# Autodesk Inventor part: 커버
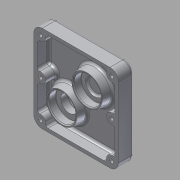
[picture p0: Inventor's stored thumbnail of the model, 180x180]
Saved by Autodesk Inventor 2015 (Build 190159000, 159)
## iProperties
Created: 2015-10
Part Number: 커버
Material: 알루미늄 6061
Document SubType Name: Modeling
Designer: mduedu
Density: 2.71 g/cm^3
Mass: 254.006 g
Surface Area: 401.286 cm^2
Volume: 93.729 cm^3
Appearance: 알루미늄 - 평지
Author: mduedu
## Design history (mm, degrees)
sketch "스케치1"
  geometry: L1 (-50, -51.5)-(50, -51.5); L2 (50, -51.5)-(50, 51.5); L3 (50, 51.5)-(-50, 51.5); L4 (-50, 51.5)-(-50, -51.5); L5 (-50, -51.5)-(50, 51.5); L6 (50, -51.5)-(-50, 51.5); 1 further point
  constraints: 12 end point, 2 midpoint, 2 parallel, 1 horizontal, 1 perpendicular
  dimensions: "d0" = 100 distance of L3.end L2.end; "d1" = 103 distance of L2.end L1.end
extrude "돌출1" new body sketch "스케치1" distance "d2" = 18; taper "d3" = 0 deg
fillet "모깎기1" dims "d4" = 10
fillet "모깎기2" dims "d5" = 3
feature "쉘1" dims "d6" = 4
sketch "스케치2"
  geometry: L1 (40, 51.5)-(-40, 51.5) reference; L2 (50, -41.5)-(50, 41.5) reference; L3 (-40, -51.5)-(40, -51.5) reference; L4 (-50, 41.5)-(-50, -41.5) reference; L5 (-50, 0)-(50, 0); L6 (0, 51.5)-(0, -51.5); C1 r 6 at (-42, 43.5); C2 r 6 at (-42, 0); C3 r 6 at (-42, -43.5); C4 r 6 at (42, -43.5); C5 r 6 at (42, 0); C6 r 6 at (42, 43.5); 1 further point
  constraints: 6 centre point, 4 end point, 4 midpoint, 4 symmetric about line, 1 equal radius, 1 point on line, 1 vertical alignment, 4 other
  dimensions: "d7" = 12 diameter of C1; "d8" = 8 distance from line of C1.centre L1; "d9" = 8 distance from line of C1.centre L4
extrude "돌출2" join sketch "스케치2" stored distance "d10" = 0; taper "d11" = 0 deg
fillet "모깎기3" dims "d12" = 3
fillet "모깎기4" dims "d13" = 3
sketch "스케치3"
  geometry: A1 r 6 centre (42, 43.5) between (36.037, 44.167) and (42.667, 37.537) reference; A2 r 6 centre (42, 0) between (42.667, 5.963) and (42.667, -5.963) reference; A3 r 6 centre (42, -43.5) between (42.667, -37.537) and (36.037, -44.167) reference; A4 r 6 centre (-42, -43.5) between (-36.037, -44.167) and (-42.667, -37.537) reference; A5 r 6 centre (-42, 0) between (-42.667, -5.963) and (-42.667, 5.963) reference; A6 r 6 centre (-42, 43.5) between (-42.667, 37.537) and (-36.037, 44.167) reference; 7 further points
  constraints: 6 coincident
hole "구멍1" sketch "스케치3" at (-42, 43.5), (-42, 0), (-42, -43.5), (42, -43.5), (42, 0), (42, 43.5) diameter "d14" = 4.5; stored, may be unused: countersink angle "d18" = 90 deg, drill point angle "d20" = 118 deg; dims "d15" = 6, "d16" = 8, "d17" = 4.4, "d19" = 8
sketch "스케치4"
  geometry: L1 (83.056, 3)-(83.056, 86) reference; L2 (73.056, 96)-(-6.944, 96) reference; C1 r 20 at (43.056, 56); 1 further point
  constraints: 1 centre point
  dimensions: "d21" = 40 diameter of C1; "d22" = 40 distance from line of C1.centre L1; "d23" = 40 distance from line of C1.centre L2
extrude "돌출3" join sketch "스케치4" distance "d24" = 11; taper "d25" = -10 deg
hole "구멍2" diameter "d28" = 22; stored, may be unused: countersink angle "d32" = 90 deg, drill point angle "d34" = 0 deg; dims "d29" = 6, "d30" = 32, "d31" = 9, "d33" = 11, "d35" = 10, "d36" = 10
sketch "스케치5"
  geometry: L1 (-40, -51.5)-(40, -51.5) reference; L2 (50, -41.5)-(50, 41.5) reference; C1 r 25 at (20, -21.5); 1 further point
  constraints: 1 centre point
  dimensions: "d37" = 50 diameter of C1; "d40" = 30 distance from line of C1.centre L1; "d41" = 30 distance from line of C1.centre L2
extrude "돌출4" join sketch "스케치5" distance "d42" = 15; taper "d43" = -10 deg
sketch "스케치6"
  geometry: C1 r 25 at (13.056, 23) reference; C2 r 20 at (13.056, 23); 1 further point
  constraints: 1 centre point, 1 coincident
  dimensions: "d44" = 40 diameter of C2
extrude "돌출5" join sketch "스케치6" distance "d45" = 11; taper "d46" = -10 deg
hole "구멍3" diameter "d49" = 20; stored, may be unused: countersink angle "d53" = 90 deg, drill point angle "d55" = 118 deg; dims "d47" = 10, "d48" = 10, "d50" = 6, "d51" = 32, "d52" = 9, "d54" = 11
hole "구멍4" diameter "d58" = 24; stored, may be unused: countersink angle "d62" = 90 deg, drill point angle "d64" = 0 deg; dims "d56" = 10, "d57" = 10, "d59" = 6, "d60" = 28, "d61" = 11, "d63" = 13
chamfer "모따기1" distance "d65" = 1; stored, may be unused: second distance "d66" = 2, angle "d67" = 45 deg
sketch "스케치7" dims "d68" = 36
  geometry: C1 r 25 at (0, 0) reference; 3 further points
  constraints: 2 vertical alignment, 1 coincident, 2 other
hole "구멍5" sketch "스케치7" at (0, 18) diameter "d69" = 2.459; stored, may be unused: countersink angle "d73" = 90 deg, drill point angle "d75" = 118 deg; dims "d70" = 8, "d71" = 28, "d72" = 11, "d74" = 10
sketch "스케치8"
  geometry: L1 (-50, 41.5)-(-50, -41.5) reference; L2 (40, 51.5)-(-40, 51.5) reference; 2 further points
  constraints: 1 other
  dimensions: "d79" = 50 distance from line of point (0, 26.5) L1; "d80" = 25 distance from line of point (0, 26.5) L2
feature "엠보싱1" sketch "스케치8" dims "d0" = 100, "d1" = 103, "d5" = 3, "d81" = 0.5, "d82" = 0
fillet "모깎기5" dims "d83" = 3
fillet "모깎기6" dims "d84" = 3
fillet "모깎기7" dims "d85" = 3
fillet "모깎기8" dims "d86" = 0.3
fillet "모깎기9" dims "d87" = 3
node "솔리드1"
pattern_circular "원형 패턴1" dims angle "d77" = 360 deg
